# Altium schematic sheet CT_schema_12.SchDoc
size 278 x 170 mm
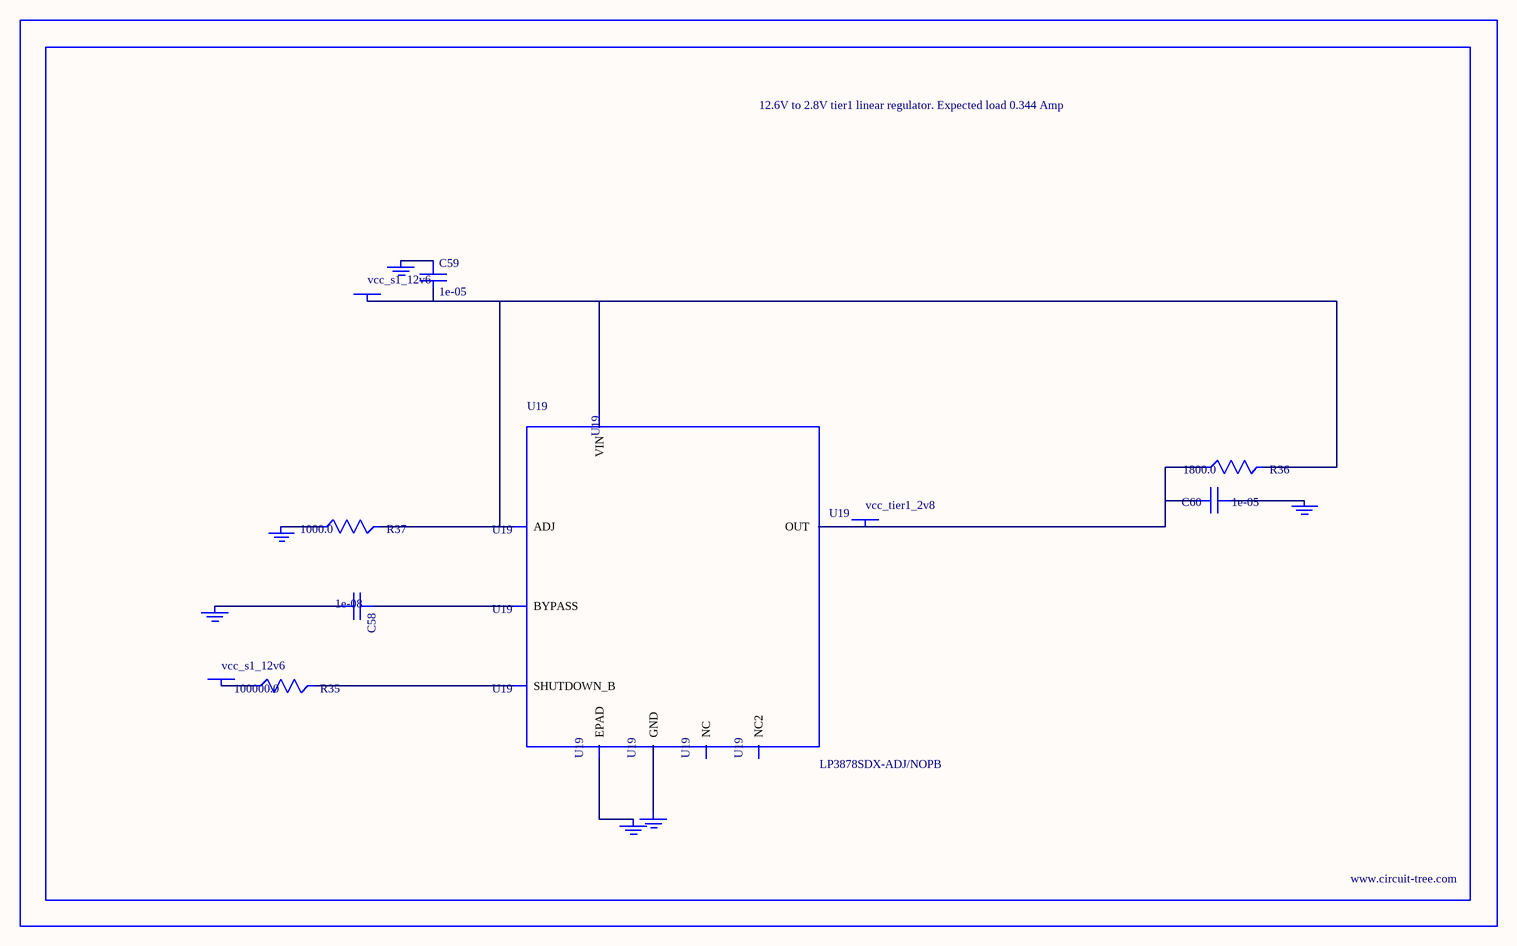
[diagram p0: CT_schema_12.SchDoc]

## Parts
BORDER11  (no value)
C58  1e-08  [C0402]
C59  1e-05  [C1210]
C60  1e-05  [C1210]
GND_INSTANCE_11_0  (no value)
GND_INSTANCE_11_1  (no value)
GND_INSTANCE_11_2  (no value)
GND_INSTANCE_11_3  (no value)
GND_INSTANCE_11_4  (no value)
GND_INSTANCE_11_5  (no value)
POWER_INSTANCE_11_0  vcc_s1_12v6
POWER_INSTANCE_11_1  vcc_s1_12v6
POWER_INSTANCE_11_2  vcc_tier1_2v8
R35  100000.0  [R0603]
R36  1800.0  [R0603]
R37  1000.0  [R0603]
U19  LP3878SDX-ADJ/NOPB  [WSON-8]

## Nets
NetC58_1: C58.1 U19.1(BYPASS)
NetC58_2: C58.2 GND_INSTANCE_11_0.0(GND)
NetC59_1: C59.1 GND_INSTANCE_11_1.0(GND)
NetC59_2: C59.2 POWER_INSTANCE_11_0.0(PWR) R36.2 R37.2 U19.4(VIN) U19.6(ADJ)
NetC60_1: C60.1 GND_INSTANCE_11_2.0(GND)
NetC60_2: C60.2 POWER_INSTANCE_11_2.0(PWR) R36.1 U19.5(OUT)
NetGND_INSTANCE_11_3_0: GND_INSTANCE_11_3.0(GND) R37.1
NetGND_INSTANCE_11_4_0: GND_INSTANCE_11_4.0(GND) U19.PAD(EPAD)
NetGND_INSTANCE_11_5_0: GND_INSTANCE_11_5.0(GND) U19.3(GND)
NetPOWER_INSTANCE_11_1_0: POWER_INSTANCE_11_1.0(PWR) R35.1
NetR35_2: R35.2 U19.8(SHUTDOWN_B)

Not connected (* = marked no-connect by the designer): U19 2(NC) 7(NC2)

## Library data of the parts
BORDER11 = BORDER_PAGE11
C58 = C0402C103K3RAC
C59 = C1210C106K5PACTU
C60 = GRM32DR61E106MA12L
GND_INSTANCE_11_0-GND_INSTANCE_11_5 = GND
POWER_INSTANCE_11_0-POWER_INSTANCE_11_2 = PWR
R35 = RC0603JR-07100KL
R36 = RC0603JR-071K8L
R37 = RC0603JR-071KL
